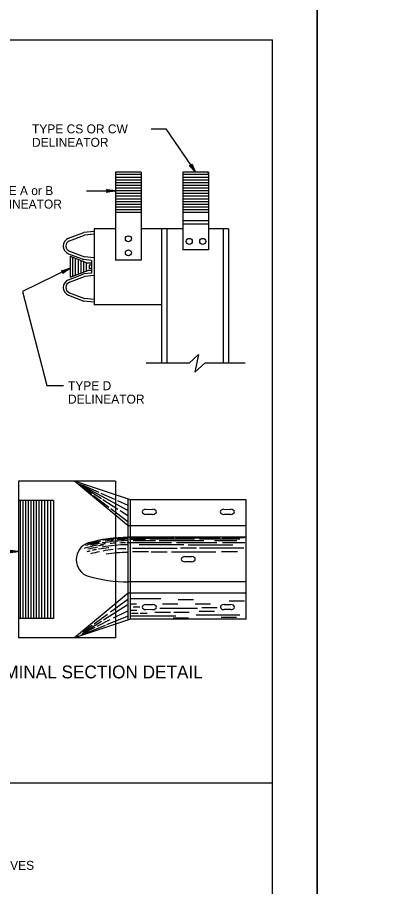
# Model space of a CAD drawing. Extents: x 640253 to 641999, y 298458 to 299646.
# Drawn here: x 640993.9 to 641116.9, y 298753 to 299044.1 of the extents above; entities that cross this region are included whole.
import ezdxf

# ---------------------------------------------------------------- set-up
doc = ezdxf.new("R2010")
doc.units = 0
for name, color, linetype in [('1', 7, 'Continuous'), ('2', 7, 'Continuous'), ('PLT-BNDY', 7, 'Continuous')]:
    doc.layers.add(name, color=color, linetype=linetype)

msp = doc.modelspace()

# ---------------------------------------------------------------- linework, layer by layer
at = {"layer": '1'}
for p, q in [((640293.31, 299036.63), (641079.31, 299036.63)), ((641079.31, 298472.63), (641079.31, 299036.63)), ((640994.25, 298888.75), (640994.25, 298836.25)), ((641026.75, 298888.75), (640994.25, 298888.75)), ((641031.75, 298882.5), (641013, 298888.75)), ((641031, 298873.75), (641013, 298888.75)), ((641014.58, 298887.88), (641030.72, 298879.02)), ((641014.77, 298887.42), (641018.82, 298884.36)), ((641015.6, 298887.58), (641021.2, 298885.08)), ((641015.79, 298886.96), (641022, 298882.97)), ((641026.75, 298888.75), (641026.75, 298884.16)), ((641019.37, 298883.95), (641024.48, 298880.09)), ((641021.85, 298884.79), (641026.4, 298882.76)), ((641026.75, 298883.98), (641026.75, 298840.92)), ((641006.01, 298882.25), (640994.25, 298882.25)), ((641006.01, 298882.25), (641006.01, 298842.75)), ((641022.53, 298882.63), (641027.57, 298879.41)), ((641027.37, 298882.32), (641030.88, 298880.76)), ((641031, 298842.25), (641031, 298882.75)), ((641070.5, 298882.5), (641031.75, 298882.5)), ((641031.75, 298842.5), (641031.75, 298882.5)), ((641070.5, 298842.5), (641070.5, 298882.5)), ((641025.16, 298879.58), (641030.86, 298875.29)), ((641028.3, 298878.93), (641030.85, 298877.3)), ((641036.94, 298879.34), (641039.18, 298879.33)), ((641063.06, 298879.34), (641065.31, 298879.33)), ((641039.17, 298877.65), (641036.93, 298877.65)), ((641065.3, 298877.65), (641063.06, 298877.65)), ((641070.5, 298873.75), (641031, 298873.75)), ((641070.5, 298870), (641031, 298870)), ((641036.74, 298869.24), (641031.39, 298869.24)), ((641046.34, 298869.59), (641031.41, 298869.59)), ((641053.17, 298869.29), (641038.23, 298869.29)), ((641061.76, 298869.64), (641046.82, 298869.64)), ((641068.33, 298869.34), (641054.84, 298869.34)), ((641069.95, 298869.74), (641062.47, 298869.74)), ((641045.44, 298868.13), (641030.5, 298868.13)), ((641047.41, 298866.26), (641032.47, 298866.26)), ((641040.08, 298868.78), (641032.6, 298868.78)), ((641049.63, 298867.42), (641034.69, 298867.42)), ((641056.3, 298868.73), (641041.36, 298868.73)), ((641060.65, 298868.13), (641047.15, 298868.13)), ((641053.88, 298866.31), (641048.52, 298866.31)), ((641066, 298867.37), (641051.07, 298867.37)), ((641069.74, 298866.31), (641054.81, 298866.31)), ((641067.42, 298868.78), (641059.94, 298868.78)), ((641070, 298868.13), (641062.52, 298868.13)), ((641037.75, 298865.09), (641032.4, 298865.09)), ((641044.07, 298865.04), (641038.71, 298865.04)), ((641060.39, 298865.04), (641045.46, 298865.04)), ((641049.98, 298863.48), (641052.22, 298863.48)), ((641067.57, 298865.14), (641062.21, 298865.14)), ((641052.21, 298861.79), (641049.97, 298861.8)), ((641070.5, 298855), (641031, 298855)), ((641031, 298851.25), (641013, 298836.25)), ((641025.08, 298845.03), (641030.87, 298849.21)), ((641070.5, 298851.25), (641031, 298851.25)), ((641031.87, 298849.46), (641041.94, 298849.46)), ((641047.73, 298849.13), (641052.91, 298849.13)), ((641022.75, 298842.32), (641030.62, 298847.36)), ((641031.98, 298847.72), (641033.73, 298847.72)), ((641032.69, 298846.68), (641034.9, 298846.68)), ((641036.94, 298847.41), (641039.18, 298847.41)), ((641041.61, 298846.25), (641054.22, 298846.25)), ((641042.47, 298847.72), (641047.65, 298847.72)), ((641053.39, 298847.72), (641058.56, 298847.72)), ((641055.61, 298846.4), (641060.79, 298846.4)), ((641063.11, 298847.45), (641065.36, 298847.45)), ((641065.35, 298845.76), (641063.11, 298845.76)), ((641064.81, 298848.63), (641069.98, 298848.63)), ((641019.56, 298841.03), (641024.04, 298844.27)), ((641023.87, 298840.74), (641030.75, 298843.59)), ((641026.12, 298842.98), (641030.87, 298845.37)), ((641031.85, 298843.63), (641046.89, 298843.63)), ((641031.87, 298845.57), (641033.89, 298845.57)), ((641032.13, 298844.56), (641034.34, 298844.56)), ((641035, 298844.56), (641037.31, 298844.56)), ((641039.17, 298845.72), (641036.93, 298845.73)), ((641039.95, 298844.89), (641045.13, 298844.89)), ((641046.05, 298843.04), (641051.23, 298843.04)), ((641046.25, 298844.91), (641051.43, 298844.91)), ((641053.74, 298844.03), (641068.42, 298844.03)), ((641054.7, 298845.19), (641059.88, 298845.19)), ((641062.08, 298843.17), (641067.26, 298843.17)), ((641006.01, 298842.75), (640994.25, 298842.75)), ((641031.75, 298842.5), (641013, 298836.25)), ((641015.14, 298837.13), (641023.34, 298840.52)), ((641015.59, 298837.75), (641022.06, 298841.88)), ((641015.94, 298838.41), (641018.89, 298840.55)), ((641020.61, 298840.19), (641024.99, 298842.39)), ((641026.75, 298840.85), (641026.75, 298836.25)), ((641070.5, 298842.5), (641031.75, 298842.5)), ((641016.01, 298837.88), (641019.88, 298839.83)), ((641026.75, 298836.25), (640994.25, 298836.25)), ((640293.31, 298787.67), (641079.31, 298787.67))]:
    msp.add_line(p, q, dxfattribs=at)
for centre, radius, start, end in [((641031.71, 298817.21), 52.79, 90.7697, 105.5487), ((641031.61, 298816.9), 52.79, 90.7697, 100.0032), ((641031.36, 298816.5), 52.79, 90.7697, 94.465), ((641019.44, 298862.5), 5.88, 108.6699, 251.835), ((641030.35, 298815.39), 52.79, 100.5386, 105.5487), ((641030.85, 298816.35), 52.79, 100.5386, 105.5487), ((641031.51, 298816.8), 52.79, 100.5386, 105.5487), ((641030.22, 298814.73), 52.79, 100.5386, 103.989), ((641031.11, 298816.07), 52.79, 100.5386, 103.989), ((641030.17, 298815.09), 52.79, 98.1369, 100.0032), ((641030.2, 298813.97), 52.79, 96.1764, 100.0032), ((641030.88, 298815.54), 52.79, 98.1369, 100.0032), ((641031.41, 298814.68), 52.79, 90.7697, 100.0032), ((641031.43, 298816.07), 52.79, 90.7697, 100.0032), ((641031.36, 298816.5), 52.79, 95.7095, 98.7189), ((641031.13, 298815.41), 52.79, 94.5197, 96.728), ((641030.93, 298813.37), 52.79, 90.7697, 93.8884), ((641030.75, 298815.31), 52.79, 90.7697, 92.7909), ((641031.33, 298814.23), 52.79, 104.3483, 105.5487), ((641031.06, 298813.22), 52.79, 100.5386, 103.9089), ((641031.33, 298814.25), 52.79, 102.1044, 103.5962), ((641031.61, 298813.37), 52.79, 96.1764, 100.0032), ((641031.46, 298812.13), 52.79, 90.7697, 98.5017), ((641031.71, 298907.78), 52.79, 254.4513, 269.2303)]:
    msp.add_arc(centre, radius, start, end, dxfattribs=at)
for centre, start_param, end_param in [((641036.94, 298878.49), 1.590592, 4.707341), ((641039.18, 298878.49), 4.732181, 7.83878), ((641063.06, 298878.5), 1.590592, 4.707341), ((641065.3, 298878.49), 4.732181, 7.83878), ((641049.97, 298862.64), 1.590592, 4.707341), ((641052.22, 298862.64), 4.732181, 7.83878), ((641036.94, 298846.57), 1.590592, 4.707341), ((641039.18, 298846.57), 4.732181, 7.83878), ((641063.11, 298846.61), 1.590592, 4.707341), ((641065.35, 298846.6), 4.732181, 7.83878)]:
    msp.add_ellipse(centre, major_axis=(1.25, 0), ratio=0.675, start_param=start_param, end_param=end_param, dxfattribs=at)
at = {"layer": '2'}
for p, q in [((641038.73, 299006.79), (641043.64, 299006.79)), ((641043.64, 299006.79), (641053.55, 298992.32)), ((641026.75, 298992.32), (641026.75, 298962.78)), ((641035.34, 298992.32), (641026.75, 298992.32)), ((641035.34, 298991.44), (641026.75, 298991.44)), ((641035.34, 298992.18), (641035.2, 298992.32)), ((641035.34, 298991.92), (641035.2, 298992.06)), ((641035.34, 298992.32), (641035.34, 298962.78)), ((641057.84, 298992.32), (641049.25, 298992.32)), ((641049.25, 298992.32), (641049.25, 298966.23)), ((641057.84, 298991.44), (641049.25, 298991.44)), ((641057.84, 298991.92), (641057.7, 298992.06)), ((641057.84, 298992.32), (641057.84, 298966.23)), ((641035.34, 298990.54), (641026.75, 298990.54)), ((641035.34, 298989.64), (641026.75, 298989.64)), ((641035.34, 298988.74), (641026.75, 298988.74)), ((641057.84, 298990.54), (641049.25, 298990.54)), ((641057.84, 298989.64), (641049.25, 298989.64)), ((641057.84, 298988.74), (641049.25, 298988.74)), ((641017.07, 298985.99), (641026.75, 298985.99)), ((641035.34, 298987.84), (641026.75, 298987.84)), ((641035.34, 298986.94), (641026.75, 298986.94)), ((641035.34, 298986.04), (641026.75, 298986.04)), ((641057.84, 298987.84), (641049.25, 298987.84)), ((641057.84, 298986.94), (641049.25, 298986.94)), ((641057.84, 298986.04), (641049.25, 298986.04)), ((641035.34, 298985.14), (641026.75, 298985.14)), ((641035.34, 298984.24), (641026.75, 298984.24)), ((641035.34, 298983.26), (641026.75, 298983.26)), ((641057.84, 298985.14), (641049.25, 298985.14)), ((641057.84, 298984.24), (641049.25, 298984.24)), ((641057.84, 298983.26), (641049.25, 298983.26)), ((641035.34, 298982.36), (641026.75, 298982.36)), ((641035.34, 298981.46), (641026.75, 298981.46)), ((641035.34, 298980.56), (641026.75, 298980.56)), ((641057.84, 298982.36), (641049.25, 298982.36)), ((641057.84, 298981.46), (641049.25, 298981.46)), ((641057.84, 298980.56), (641049.25, 298980.56)), ((641035.34, 298979.66), (641026.75, 298979.66)), ((641035.34, 298978.76), (641026.75, 298978.76)), ((641057.84, 298979.66), (641049.25, 298979.66)), ((641057.84, 298978.76), (641049.25, 298978.76)), ((641057.84, 298975.96), (641049.25, 298975.96)), ((641057.84, 298974.89), (641049.25, 298974.89)), ((641011.02, 298970.14), (641016.09, 298972.1)), ((641011.34, 298969.3), (641016.3, 298971.22)), ((641019.6, 298972.45), (641016.09, 298972.1)), ((641019.6, 298971.54), (641016.3, 298971.22)), ((641019.6, 298973.35), (641019.6, 298947.85)), ((641026.75, 298973.35), (641019.6, 298973.35)), ((641042.1, 298973.35), (641035.34, 298973.35)), ((641042.1, 298973.35), (641042.1, 298928.35)), ((641049.25, 298973.35), (641042.1, 298973.35)), ((641043.9, 298973.35), (641043.9, 298928.35)), ((641064.6, 298973.35), (641057.84, 298973.35)), ((641062.8, 298973.35), (641062.8, 298928.35)), ((641064.6, 298973.35), (641064.6, 298928.35)), ((641011.34, 298965.78), (641016.3, 298963.86)), ((641057.84, 298966.23), (641049.25, 298966.23)), ((641011.02, 298964.94), (641016.09, 298962.98)), ((641011.55, 298964.12), (641017.49, 298961.83)), ((641011.55, 298964.12), (641011.55, 298957.07)), ((641012.43, 298957.41), (641012.43, 298963.78)), ((641013.37, 298957.78), (641013.37, 298963.42)), ((641014.32, 298958.14), (641014.32, 298963.05)), ((641015.22, 298958.49), (641015.22, 298962.7)), ((641018.7, 298962.73), (641016.09, 298962.98)), ((641016.12, 298958.84), (641016.12, 298962.36)), ((641019.6, 298963.54), (641016.3, 298963.86)), ((641018.7, 298962.73), (641018.7, 298958.47)), ((641035.34, 298962.78), (641026.75, 298962.78)), ((641011.55, 298960.09), (640995.61, 298952.27)), ((641011.55, 298957.07), (641017.49, 298959.36)), ((641017.02, 298959.18), (641017.02, 298962.01)), ((641018.7, 298961.83), (641017.49, 298961.83)), ((641018.7, 298959.36), (641017.49, 298959.36)), ((641017.93, 298961.15), (641017.93, 298960.04)), ((641018.7, 298961.15), (641017.93, 298961.15)), ((641018.7, 298960.04), (641017.93, 298960.04)), ((641018.7, 298961.83), (641018.7, 298961.15)), ((641018.7, 298960.04), (641018.7, 298959.36)), ((641011.02, 298956.25), (641016.09, 298958.21)), ((641011.34, 298955.41), (641016.3, 298957.33)), ((641018.7, 298958.47), (641016.09, 298958.21)), ((641019.6, 298957.65), (641016.3, 298957.33)), ((640995.61, 298952.27), (641003.72, 298920.79)), ((641011.02, 298951.05), (641016.09, 298949.09)), ((641011.34, 298951.89), (641016.3, 298949.97)), ((641019.6, 298948.75), (641016.09, 298949.09)), ((641019.6, 298949.65), (641016.3, 298949.97)), ((641042.1, 298947.85), (641019.6, 298947.85)), ((641051.38, 298928.35), (641054.56, 298931.19)), ((641054.56, 298931.19), (641053.32, 298925.29)), ((641051.38, 298928.35), (641037.06, 298928.35)), ((641053.32, 298925.29), (641056.66, 298928.35)), ((641070.15, 298928.35), (641056.66, 298928.35)), ((641003.72, 298920.79), (641009.3, 298920.79)), ((640994.9, 298842.75), (640994.9, 298882.25)), ((640995.8, 298842.75), (640995.8, 298882.25)), ((640996.7, 298842.75), (640996.7, 298882.25)), ((640997.6, 298842.75), (640997.6, 298882.25)), ((640998.5, 298842.75), (640998.5, 298882.25)), ((640999.4, 298842.75), (640999.4, 298882.25)), ((641000.3, 298842.75), (641000.3, 298882.25)), ((641001.2, 298842.75), (641001.2, 298882.25)), ((641002.1, 298842.75), (641002.1, 298882.25)), ((641003.1, 298842.75), (641003.1, 298882.25)), ((641004.1, 298842.75), (641004.1, 298882.25)), ((641005.1, 298842.75), (641005.1, 298882.25)), ((640973.4, 298865.2), (640994.25, 298865.2))]:
    msp.add_line(p, q, dxfattribs=at)
for points in [[(641052.23, 298994.88), (641052.12, 298994.67), (641053.55, 298992.32), (641052.23, 298994.88), (641052.25, 298995.07), (641053.55, 298992.32), (641051.88, 298994.51), (641051.66, 298994.47), (641053.55, 298992.32), (641051.46, 298994.52), (641051.66, 298994.47)], [(641023.9, 298986.35), (641024, 298986.14), (641026.75, 298985.99), (641023.9, 298986.35), (641023.75, 298986.47), (641026.75, 298985.99), (641024.01, 298985.85), (641023.91, 298985.65), (641026.75, 298985.99), (641023.75, 298985.51), (641023.91, 298985.65)], [(641008.83, 298959.15), (641009.02, 298959.01), (641011.55, 298960.09), (641008.83, 298959.15), (641008.64, 298959.2), (641011.55, 298960.09), (641009.15, 298958.75), (641009.15, 298958.53), (641011.55, 298960.09), (641009.07, 298958.34), (641009.15, 298958.53)], [(640991.4, 298865.56), (640991.5, 298865.35), (640994.25, 298865.2), (640991.4, 298865.56), (640991.25, 298865.69), (640994.25, 298865.2), (640991.51, 298865.07), (640991.41, 298864.86), (640994.25, 298865.2), (640991.25, 298864.73), (640991.41, 298864.86)]]:
    msp.add_lwpolyline(points, dxfattribs=at)
for centre in [(641031.05, 298969.97), (641051.45, 298969.1), (641055.94, 298969.1), (641031.05, 298965.27)]:
    msp.add_circle(centre, 1, dxfattribs=at)
for centre, radius in [((641012.02, 298967.54), 2.79), ((641012.02, 298967.54), 1.89), ((641012.02, 298953.65), 2.79), ((641012.02, 298953.65), 1.89)]:
    msp.add_arc(centre, radius, 111.1095, 248.8905, dxfattribs=at)
at = {"layer": 'PLT-BNDY'}
for points in [[(640253.31, 299051.63), (641094.31, 299051.63), (641094.31, 298457.63), (640253.31, 298457.63)], [(641094.31, 299051.63), (641935.31, 299051.63), (641935.31, 298457.63), (641094.31, 298457.63)]]:
    msp.add_lwpolyline(points, close=True, dxfattribs=at)

# ---------------------------------------------------------------- texts
at = {"layer": '2'}
for s, height, p in [('TYPE CS OR CW', 3, (640998.77, 299005.27)), ('DELINEATOR', 3, (640998.77, 299000.77)), ('TYPE A or B', 3, (640983.15, 298984.59)), ('DELINEATOR', 3, (640983.15, 298980.09)), ('TYPE D', 3, (641010.82, 298919.25)), ('DELINEATOR', 3, (641010.82, 298914.75)), ('TERMINAL SECTION DETAIL', 4.3, (640977.99, 298822.71)), ("INSTALL DELINEATORS ON GUIDE RAIL AT 11.43 m (37.5') SPACING ON HORIZONTAL CURVES", 3, (640817.48, 298758.57))]:
    msp.add_text(s, height=height, dxfattribs=at).set_placement(p)

doc.saveas('drawing.dxf')
